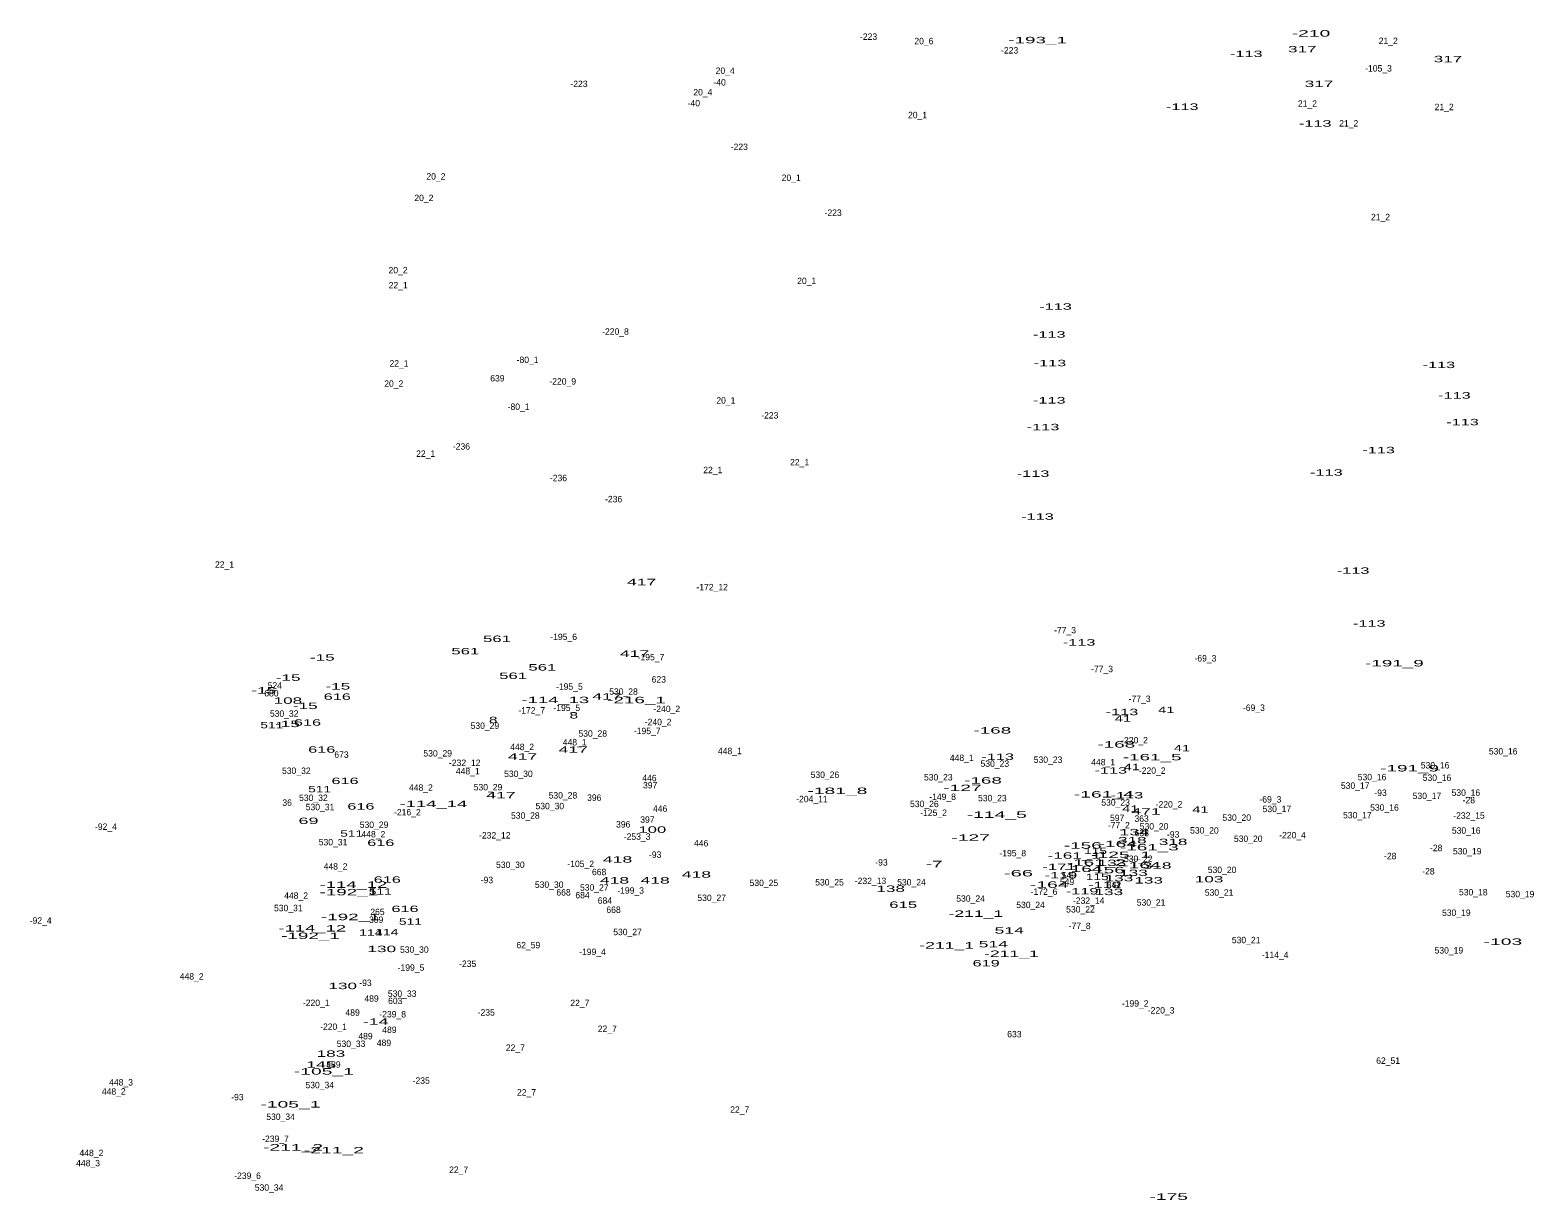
# Model space of a CAD drawing. Extents: x -661742 to -657295, y -1002932 to -996888.
# Drawn here: x -659741 to -658802, y -999094 to -998364 of the extents above; entities that cross this region are included whole.
import ezdxf
from ezdxf.enums import TextEntityAlignment as Align

# ---------------------------------------------------------------- set-up
doc = ezdxf.new("R2010")
doc.units = 0
doc.header["$LTSCALE"] = 1.6
doc.layers.add('24', color=7, linetype='Continuous')

msp = doc.modelspace()

# ---------------------------------------------------------------- texts
at = {"layer": '24'}
for s, width, p in [('-210', 2.25, (-658941.387, -998368.02)), ('-193_1', 2.2, (-659111.963, -998372.19)), ('317', 2, (-658946.793, -998377.86)), ('-113', 1.9, (-658981.777, -998380.8)), ('317', 2, (-658855.903, -998384.05)), ('317', 2, (-658936.353, -998399.53)), ('-113', 1.9, (-659021.717, -998413.77)), ('-113', 1.9, (-658938.737, -998424.25)), ('-113', 1.9, (-659100.817, -998538.48)), ('-113', 1.9, (-659104.687, -998555.94)), ('-113', 1.9, (-659104.307, -998573.78)), ('-113', 1.9, (-658861.577, -998574.94)), ('-113', 1.9, (-658851.887, -998593.95)), ('-113', 1.9, (-659104.687, -998597.05)), ('-113', 1.9, (-658846.847, -998610.63)), ('-113', 1.9, (-659108.567, -998613.73)), ('-113', 1.9, (-658899.197, -998628.08)), ('-113', 1.9, (-659114.777, -998642.82)), ('-113', 1.9, (-658931.767, -998642.05)), ('-113', 1.9, (-659112.057, -998669.59)), ('-113', 1.9, (-658915.087, -998703.33)), ('417', 2.05, (-659359.008, -998710.45)), ('-113', 1.9, (-658905.007, -998736.3)), ('561', 1.95, (-659469.073, -998753.63)), ('561', 1.95, (-659449.293, -998745.87)), ('-113', 1.9, (-659086.077, -998748.12)), ('-15', 2, (-659558.281, -998757.52)), ('561', 1.95, (-659420.983, -998763.71)), ('417', 2.05, (-659363.448, -998755.15)), ('-191_9', 2.2, (-658889.337, -998761.14)), ('-15', 2, (-659579.611, -998770.12)), ('561', 1.95, (-659439.203, -998768.96)), ('-15', 2, (-659594.821, -998778.08)), ('616', 1.9, (-659548.937, -998782.01)), ('-15', 2, (-659548.591, -998775.56)), ('417', 2.05, (-659380.668, -998781.84)), ('108', 2, (-659579.754, -998784.47)), ('-15', 2, (-659568.951, -998787.77)), ('-114_13', 2.15, (-659412.889, -998784.04)), ('-216_1', 2.2, (-659362.243, -998784.1)), ('-113', 1.9, (-659059.327, -998791.57)), ('41', 1.7, (-659031.643, -998790.2)), ('511', 1.6, (-659589.804, -998799.74)), ('-15', 2, (-659580.001, -998799.02)), ('616', 1.9, (-659567.547, -998798.11)), ('8', 1.8, (-659451.661, -998796.54)), ('8', 1.8, (-659401.381, -998793.64)), ('41', 1.7, (-659058.723, -998795.62)), ('-168', 2.2, (-659140.205, -998803.04)), ('616', 1.9, (-659558.637, -998814.98)), ('417', 2.05, (-659433.268, -998819.32)), ('417', 2.05, (-659401.748, -998815.06)), ('-113', 1.9, (-659136.877, -998819.49)), ('-168', 2.2, (-659062.855, -998811.77)), ('-161_5', 2.2, (-659040.483, -998819.74)), ('41', 1.7, (-659021.873, -998814.09)), ('-113', 1.9, (-659066.307, -998828.03)), ('41', 1.7, (-659053.203, -998825.89)), ('-191_9', 2.2, (-658879.837, -998826.69)), ('616', 1.9, (-659544.097, -998834.57)), ('-168', 2.2, (-659146.025, -998834.27)), ('511', 1.6, (-659559.954, -998839.69)), ('417', 2.05, (-659446.808, -998843.5)), ('-181_8', 2.25, (-659236.887, -998840.74)), ('-127', 2.25, (-659158.905, -998838.93)), ('-161_4', 2.25, (-659070.638, -998842.96)), ('-113', 1.9, (-659056.227, -998843.54)), ('616', 1.9, (-659534.207, -998850.47)), ('-114_14', 2.15, (-659488.955, -998848.88)), ('-114_5', 2.25, (-659137.443, -998855.64)), ('41', 1.7, (-659054.173, -998851.91)), ('471', 2.05, (-659044.288, -998853.61)), ('41', 1.7, (-659010.373, -998852.4)), ('69', 2.1, (-659566.901, -998859.48)), ('100', 1.95, (-659352.37, -998864.99)), ('134', 2.05, (-659051.723, -998866.54)), ('511', 1.6, (-659539.984, -998867.41)), ('616', 1.9, (-659521.797, -998873.16)), ('-127', 2.25, (-659153.775, -998869.96)), ('-156', 2.2, (-659083.765, -998874.85)), ('-164', 2.25, (-659061.961, -998873.91)), ('318', 2, (-659052.837, -998871.57)), ('-161_3', 2.2, (-659042.213, -998875.95)), ('318', 2, (-659027.407, -998872.63)), ('418', 2.05, (-659374.043, -998883.59)), ('-161_1', 2, (-659089.129, -998881.15)), ('-161_2', 2.2, (-659075.373, -998885.51)), ('115', 1.6, (-659075.824, -998878.26)), ('-125_1', 2.25, (-659059.857, -998880.69)), ('133', 2, (-659065.567, -998885.75)), ('418', 2.05, (-659324.833, -998892.97)), ('-7', 2.2, (-659176.479, -998886.47)), ('-66', 2.35, (-659123.913, -998892.2)), ('-171', 1.95, (-659098.601, -998888.24)), ('-119', 1.9, (-659097.381, -998893.48)), ('-164', 2.25, (-659083.431, -998889.48)), ('115', 1.6, (-659074.754, -998894.51)), ('-156', 2.2, (-659069.365, -998890.23)), ('133', 2, (-659052.137, -998891.94)), ('-164', 2.25, (-659047.131, -998887.2)), ('318', 2, (-659037.377, -998887.43)), ('-192_1', 2.2, (-659541.733, -998903.99)), ('-114_12', 2.15, (-659538.859, -998899.34)), ('511', 1.6, (-659522.144, -998903.57)), ('616', 1.9, (-659517.727, -998896.19)), ('418', 2.05, (-659375.983, -998896.65)), ('418', 2.05, (-659350.643, -998896.65)), ('138', 2, (-659203.647, -998901.88)), ('-164', 2.25, (-659104.711, -998899.32)), ('-119', 1.9, (-659084.191, -998903.47)), ('-119', 1.9, (-659070.241, -998899.5)), ('133', 2, (-659067.507, -998903.87)), ('133', 2, (-659061.177, -998895.27)), ('133', 2, (-659042.657, -998896.63)), ('103', 2, (-659004.984, -998895.94)), ('615', 1.95, (-659195.843, -998911.85)), ('-192_1', 2.2, (-659540.863, -998919.51)), ('616', 1.9, (-659506.677, -998914.42)), ('511', 1.6, (-659503.334, -998922.38)), ('-211_1', 2.05, (-659150.494, -998917.43)), ('-114_12', 2.15, (-659564.539, -998926.59)), ('-192_1', 2.2, (-659565.673, -998931.24)), ('114', 1.65, (-659527.989, -998929.19)), ('114', 1.65, (-659518.079, -998928.95)), ('514', 2.05, (-659129.683, -998927.88)), ('130', 2, (-659521.174, -998939.45)), ('-211_1', 2.05, (-659168.714, -998937.21)), ('514', 2.05, (-659139.573, -998936.47)), ('-103', 2.25, (-658821.637, -998934.93)), ('619', 1.9, (-659144.077, -998948.39)), ('-211_1', 2.05, (-659128.294, -998942.45)), ('130', 2, (-659545.544, -998962.56)), ('-14', 2.05, (-659524.976, -998984.81)), ('183', 2, (-659552.917, -999004.81)), ('-105_1', 2.25, (-659557.314, -999015.87)), ('145', 2.05, (-659559.163, -999011.61)), ('-105_1', 2.25, (-659578.184, -999036.43)), ('-211_2', 2.25, (-659576.547, -999063.29)), ('-211_2', 2.25, (-659551.057, -999065.04)), ('-175', 2.25, (-659030.155, -999094.06))]:
    msp.add_text(s, height=4, dxfattribs=dict(at, width=width)).set_placement(p, align=Align.CENTER)
for s, p in [('-223', (-659217.435, -998370.07)), ('20_6', (-659182.914, -998372.81)), ('-223', (-659129.425, -998378.6)), ('21_2', (-658893.169, -998372.65)), ('20_4', (-659306.894, -998391.34)), ('-105_3', (-658899.26, -998389.86)), ('-223', (-659398.125, -998399.55)), ('20_4', (-659320.844, -998404.75)), ('-40', (-659310.393, -998398.58)), ('-40', (-659326.483, -998411.57)), ('21_2', (-658943.589, -998411.82)), ('21_2', (-658858.309, -998413.97)), ('20_1', (-659186.863, -998418.97)), ('21_2', (-658917.849, -998424.16)), ('-223', (-659298.085, -998438.84)), ('20_2', (-659487.399, -998457.29)), ('20_1', (-659265.703, -998458.13)), ('20_2', (-659494.899, -998470.71)), ('-223', (-659239.535, -998479.96)), ('21_2', (-658897.999, -998482.65)), ('20_2', (-659510.999, -998515.78)), ('22_1', (-659510.949, -998525.17)), ('20_1', (-659256.053, -998522.52)), ('-220_8', (-659375.366, -998554.11)), ('22_1', (-659510.409, -998573.99)), ('-80_1', (-659430.19, -998571.74)), ('639', (-659449.048, -998583.28)), ('-220_9', (-659408.282, -998585.24)), ('20_2', (-659513.679, -998586.6)), ('-80_1', (-659435.81, -998601.03)), ('20_1', (-659306.473, -998597.1)), ('-223', (-659279.085, -998606.41)), ('22_1', (-659493.779, -998630.33)), ('-236', (-659471.47, -998625.81)), ('22_1', (-659314.639, -998640.53)), ('22_1', (-659260.469, -998635.7)), ('-236', (-659410.93, -998645.54)), ('-236', (-659376.51, -998658.7)), ('22_1', (-659619.289, -998699.55)), ('-172_12', (-659315.035, -998713.63)), ('-195_6', (-659407.687, -998744.67)), ('-77_3', (-659094.844, -998740.48)), ('-195_7', (-659353.227, -998757.38)), ('-69_3', (-659007.243, -998758.06)), ('623', (-659348.313, -998771.21)), ('-77_3', (-659071.774, -998764.72)), ('680', (-659590.047, -998779.86)), ('524', (-659587.921, -998775)), ('-195_5', (-659404.122, -998775.7)), ('530_28', (-659370.349, -998778.82)), ('-172_7', (-659427.627, -998790.56)), ('-195_5', (-659405.772, -998788.99)), ('-240_2', (-659343.341, -998789.62)), ('-77_3', (-659048.314, -998783.34)), ('-69_3', (-658977.003, -998788.9)), ('530_32', (-659582.069, -998792.55)), ('530_29', (-659456.834, -998800.11)), ('-240_2', (-659348.751, -998797.84)), ('448_1', (-659400.808, -998810.47)), ('530_28', (-659389.539, -998805)), ('-195_7', (-659355.547, -998803.4)), ('-220_2', (-659051.506, -998809.17)), ('673', (-659546.318, -998818.18)), ('530_29', (-659486.304, -998817.37)), ('448_2', (-659433.604, -998813.38)), ('448_1', (-659303.988, -998815.9)), ('530_16', (-658821.468, -998816.1)), ('530_32', (-659574.509, -998828.24)), ('-232_12', (-659469.425, -998823.27)), ('448_1', (-659467.508, -998828.51)), ('448_1', (-659159.288, -998820.17)), ('530_23', (-659138.659, -998823.78)), ('530_23', (-659105.469, -998821.35)), ('448_1', (-659071.078, -998822.88)), ('-220_2', (-659040.456, -998828.18)), ('530_16', (-658863.928, -998824.83)), ('448_2', (-659496.774, -998838.76)), ('530_29', (-659454.894, -998838.51)), ('530_30', (-659435.913, -998830.14)), ('446', (-659354.191, -998832.79)), ('397', (-659353.708, -998837.26)), ('530_26', (-659244.664, -998830.73)), ('530_23', (-659173.939, -998832.31)), ('530_17', (-658913.798, -998837.53)), ('530_16', (-658903.278, -998832.18)), ('530_16', (-658862.758, -998832.58)), ('36', (-659580.243, -998848.14)), ('530_32', (-659563.849, -998845.11)), ('530_28', (-659408.149, -998843.59)), ('396', (-659388.608, -998845.04)), ('-204_11', (-659252.787, -998845.88)), ('-149_8', (-659171.256, -998844.5)), ('530_23', (-659140.209, -998845.31)), ('530_23', (-659063.309, -998848.01)), ('-69_3', (-658966.733, -998846.11)), ('-93', (-658897.98, -998841.97)), ('530_17', (-658869.018, -998843.93)), ('530_16', (-658844.728, -998841.89)), ('-28', (-658842.895, -998846.57)), ('530_31', (-659559.723, -998850.89)), ('-216_2', (-659505.202, -998854.12)), ('530_28', (-659431.609, -998856.2)), ('530_30', (-659416.333, -998850.28)), ('446', (-659347.501, -998851.89)), ('530_26', (-659182.624, -998848.96)), ('-125_2', (-659176.916, -998854.44)), ('597', (-659062.308, -998857.64)), ('-220_2', (-659029.986, -998849.22)), ('530_20', (-658987.723, -998857.51)), ('530_17', (-658962.658, -998852.08)), ('530_17', (-658912.448, -998855.96)), ('530_16', (-658895.528, -998851.19)), ('-232_15', (-658842.795, -998856.17)), ('-92_4', (-659693.312, -998863.14)), ('530_29', (-659525.984, -998861.95)), ('396', (-659370.528, -998861.68)), ('397', (-659355.458, -998858.73)), ('-77_2', (-659061.294, -998862.21)), ('363', (-659047.073, -998858.13)), ('530_20', (-659039.293, -998862.94)), ('530_20', (-659007.883, -998865.46)), ('530_16', (-658844.538, -998865.54)), ('530_31', (-659551.583, -998872.81)), ('448_2', (-659526.434, -998867.85)), ('-232_12', (-659450.665, -998868.54)), ('-253_3', (-659361.842, -998869.34)), ('446', (-659321.911, -998873.51)), ('638', (-659046.963, -998867.1)), ('-93', (-659027.37, -998867.99)), ('530_20', (-658980.553, -998870.7)), ('-220_4', (-658952.891, -998868.42)), ('-28', (-658863.255, -998876.44)), ('-93', (-659350.58, -998880.6)), ('-93', (-659209.39, -998885.43)), ('-195_8', (-659127.472, -998879.67)), ('530_22', (-659049.149, -998883.17)), ('-28', (-658891.945, -998881.48)), ('530_19', (-658843.898, -998878.46)), ('448_2', (-659550.024, -998887.94)), ('530_30', (-659440.963, -998886.93)), ('-105_2', (-659397.06, -998886.39)), ('668', (-659385.568, -998891.43)), ('549', (-659092.507, -998893.47)), ('530_20', (-658996.833, -998890.09)), ('-28', (-658868.095, -998890.99)), ('-93', (-659455.57, -998896.43)), ('530_30', (-659416.723, -998899.35)), ('668', (-659407.768, -998904.13)), ('530_27', (-659388.584, -998901.13)), ('-199_3', (-659365.917, -998902.97)), ('530_25', (-659282.759, -998898.24)), ('530_25', (-659241.809, -998897.86)), ('-232_13', (-659216.235, -998897)), ('530_24', (-659190.664, -998897.83)), ('-172_6', (-659107.957, -998903.7)), ('549', (-659093.577, -998897.58)), ('342', (-659064.321, -998899.52)), ('530_21', (-658998.703, -998904.24)), ('530_18', (-658840.123, -998904.06)), ('530_31', (-659579.503, -998913.92)), ('448_2', (-659574.644, -998906.17)), ('684', (-659395.917, -998905.9)), ('684', (-659381.957, -998909.29)), ('530_27', (-659315.344, -998907.53)), ('530_24', (-659153.784, -998908)), ('530_24', (-659116.364, -998911.98)), ('-232_14', (-659080.109, -998909.31)), ('530_21', (-659041.153, -998910.44)), ('530_19', (-658810.948, -998905.22)), ('-92_4', (-659734.032, -998921.71)), ('309', (-659524.687, -998921.21)), ('265', (-659523.883, -998916.3)), ('668', (-659376.558, -998914.99)), ('530_22', (-659085.219, -998914.73)), ('530_19', (-658850.688, -998916.86)), ('530_27', (-659367.844, -998928.87)), ('-77_8', (-659085.754, -998925.11)), ('530_30', (-659500.863, -998939.88)), ('62_59', (-659429.746, -998937.08)), ('-199_4', (-659389.691, -998941.28)), ('530_21', (-658981.833, -998933.91)), ('530_19', (-658855.338, -998940.33)), ('-199_5', (-659502.957, -998951.1)), ('-235', (-659467.585, -998948.69)), ('-114_4', (-658963.738, -998943.17)), ('448_2', (-659639.784, -998956.59)), ('-93', (-659531.35, -998960.58)), ('530_33', (-659508.459, -998967.37)), ('-220_1', (-659562.07, -998973.08)), ('489', (-659539.387, -998979.13)), ('489', (-659527.567, -998970.41)), ('603', (-659512.787, -998971.88)), ('-235', (-659455.985, -998979.07)), ('22_7', (-659397.6, -998973.18)), ('-199_2', (-659051.057, -998973.48)), ('-220_3', (-659034.886, -998977.78)), ('-220_1', (-659551.31, -998988.01)), ('-239_8', (-659514.398, -998980.22)), ('489', (-659531.347, -998993.87)), ('489', (-659519.807, -998998.04)), ('489', (-659516.417, -998989.9)), ('22_7', (-659380.44, -998989.28)), ('633', (-659126.463, -998992.62)), ('530_33', (-659540.349, -998998.64)), ('22_7', (-659437.83, -999001.08)), ('489', (-659551.317, -999011.62)), ('62_51', (-658893.244, -999009.19)), ('448_3', (-659683.894, -999022.71)), ('530_34', (-659559.884, -999024.41)), ('-235', (-659496.595, -999021.63)), ('448_2', (-659688.404, -999028.4)), ('-93', (-659611.27, -999031.94)), ('22_7', (-659430.86, -999028.98)), ('530_34', (-659584.314, -999044.19)), ('22_7', (-659297.84, -999039.71)), ('-239_7', (-659587.484, -999057.95)), ('448_3', (-659704.444, -999073.13)), ('448_2', (-659702.364, -999066.79)), ('-239_6', (-659604.943, -999081.01)), ('22_7', (-659473.23, -999077.27)), ('530_34', (-659591.494, -999088.38))]:
    msp.add_text(s, height=4, dxfattribs=at).set_placement(p, align=Align.CENTER)

doc.saveas('drawing.dxf')
